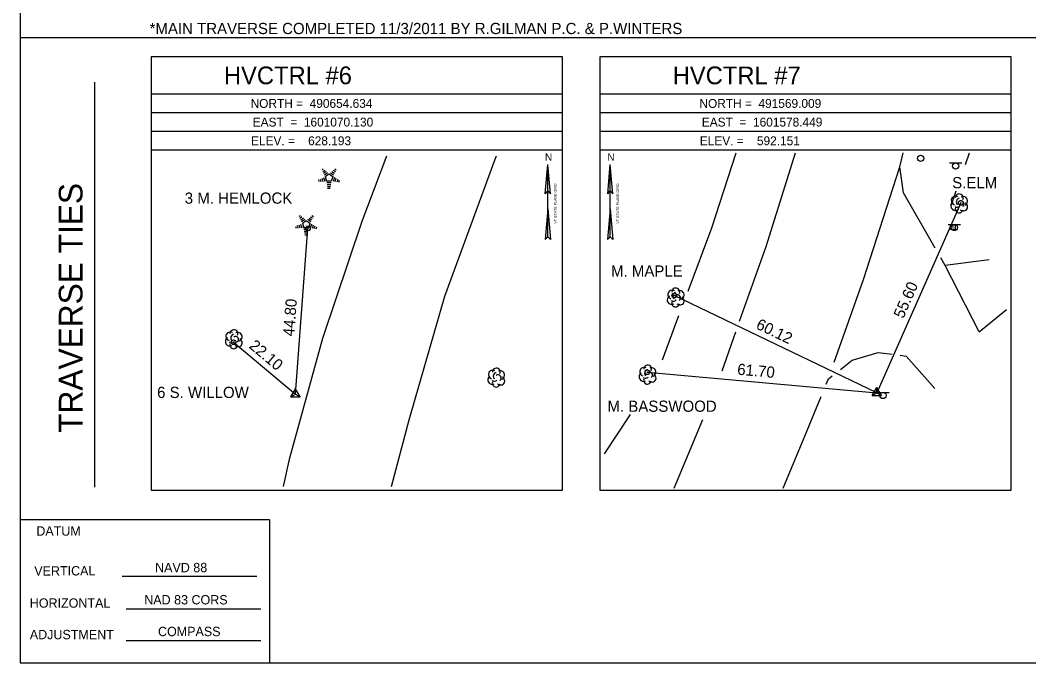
# Model space of a CAD drawing. Extents: x 1598730 to 1599370, y 501440 to 502728.
# Drawn here: x 1598729.5 to 1598999.2, y 502307.8 to 502479.8 of the extents above; entities that cross this region are included whole.
import ezdxf

# ---------------------------------------------------------------- set-up
doc = ezdxf.new("R2010")
doc.units = 0
for name, color, linetype in [('CBP', 7, 'Continuous'), ('CPSM', 7, 'Continuous'), ('Default', 7, 'Continuous'), ('L_C', 7, 'Continuous'), ('LAWA', 7, 'Continuous'), ('LTC', 7, 'Continuous'), ('LTD', 7, 'Continuous'), ('NBL1', 7, 'Continuous'), ('NBL2', 7, 'Continuous'), ('NNA_P', 7, 'Continuous'), ('PET', 7, 'Continuous'), ('RDG', 7, 'Continuous'), ('SRM', 7, 'Continuous'), ('SSGN', 7, 'Continuous'), ('UTMH', 7, 'Continuous')]:
    doc.layers.add(name, color=color, linetype=linetype)

msp = doc.modelspace()

# ---------------------------------------------------------------- linework, layer by layer
at = {"layer": 'CBP'}
for centre, radius in [((1598981.02, 502430.88), 0.625), ((1598981.02, 502430.88), 0.0833), ((1598806.48, 502424.07), 0.625), ((1598806.48, 502424.07), 0.0833), ((1598904.42, 502406.08), 0.625), ((1598904.42, 502406.08), 0.0833), ((1598786.58, 502393.61), 0.625), ((1598786.58, 502393.61), 0.0833), ((1598897.23, 502385.57), 0.625), ((1598897.23, 502385.57), 0.0833)]:
    msp.add_circle(centre, radius, dxfattribs=at)
at = {"layer": 'CPSM'}
for p, q in [((1598801.88, 502379.01), (1598803.13, 502381.17)), ((1598801.88, 502379.01), (1598803.13, 502379.73)), ((1598804.38, 502379.01), (1598803.13, 502381.17)), ((1598803.13, 502379.73), (1598803.13, 502381.17)), ((1598803.13, 502379.73), (1598803.13, 502379.73)), ((1598803.13, 502379.73), (1598804.38, 502379.01)), ((1598957.38, 502379.35), (1598958.63, 502381.52)), ((1598957.38, 502379.35), (1598958.63, 502380.08)), ((1598959.88, 502379.35), (1598958.63, 502381.52)), ((1598958.63, 502380.08), (1598958.63, 502381.52)), ((1598958.63, 502380.08), (1598958.63, 502380.08)), ((1598958.63, 502380.08), (1598959.88, 502379.35)), ((1598801.88, 502379.01), (1598804.38, 502379.01)), ((1598957.38, 502379.35), (1598959.88, 502379.35))]:
    msp.add_line(p, q, dxfattribs=at)
at = {"layer": 'Default'}
for p, q in [((1598981.02, 502430.88), (1598958.63, 502380.08)), ((1598803.13, 502379.73), (1598806.48, 502424.07)), ((1598958.63, 502380.08), (1598904.42, 502406.08)), ((1598786.58, 502393.61), (1598803.13, 502379.73)), ((1598897.23, 502385.57), (1598958.63, 502380.08))]:
    msp.add_line(p, q, dxfattribs=at)
at = {"layer": 'LAWA'}
for points in [[(1598908.11, 502407.27), (1598914.45, 502424.21), (1598921, 502444.27)], [(1598982.3, 502441.19), (1598983.37, 502444.27)], [(1598978.51, 502430.36), (1598979.83, 502434.12)], [(1598901.24, 502388.92), (1598905.65, 502400.72)], [(1598885.77, 502363.77), (1598892.69, 502374.3)]]:
    msp.add_lwpolyline(points, dxfattribs=at)
at = {"layer": 'LTC'}
for p, q in [((1598810.24, 502439.76), (1598810.59, 502440.02)), ((1598810.45, 502439.29), (1598810.98, 502439.68)), ((1598810.66, 502438.83), (1598811.36, 502439.34)), ((1598810.87, 502438.36), (1598811.75, 502439)), ((1598812.52, 502438.96), (1598813.33, 502438.37)), ((1598812.9, 502439.3), (1598813.57, 502438.81)), ((1598813.27, 502439.65), (1598813.82, 502439.25)), ((1598813.64, 502440), (1598814.06, 502439.7)), ((1598809.27, 502437.04), (1598809.42, 502436.57)), ((1598809.73, 502437.26), (1598809.94, 502436.6)), ((1598810.18, 502437.47), (1598810.45, 502436.64)), ((1598810.64, 502437.69), (1598810.97, 502436.67)), ((1598811.09, 502437.91), (1598812.1, 502438.64)), ((1598811.09, 502437.91), (1598811.48, 502436.71)), ((1598812.71, 502436.71), (1598811.48, 502436.71)), ((1598812.67, 502436.21), (1598811.53, 502436.21)), ((1598812.1, 502438.64), (1598813.1, 502437.92)), ((1598813.1, 502437.92), (1598812.71, 502436.71)), ((1598813.54, 502437.65), (1598813.2, 502436.61)), ((1598813.98, 502437.4), (1598813.7, 502436.51)), ((1598814.43, 502437.15), (1598814.19, 502436.42)), ((1598814.87, 502436.9), (1598814.69, 502436.32)), ((1598812.59, 502435.71), (1598811.6, 502435.71)), ((1598812.5, 502435.21), (1598811.67, 502435.21)), ((1598812.42, 502434.71), (1598811.75, 502434.71)), ((1598804.12, 502427.3), (1598804.48, 502427.55)), ((1598804.33, 502426.83), (1598804.86, 502427.21)), ((1598804.54, 502426.36), (1598805.25, 502426.88)), ((1598804.75, 502425.9), (1598805.63, 502426.54)), ((1598804.98, 502425.44), (1598805.99, 502426.18)), ((1598804.98, 502425.44), (1598805.36, 502424.25)), ((1598805.99, 502426.18), (1598806.99, 502425.45)), ((1598806.41, 502426.49), (1598807.22, 502425.9)), ((1598806.99, 502425.45), (1598806.59, 502424.25)), ((1598806.78, 502426.84), (1598807.46, 502426.35)), ((1598807.15, 502427.19), (1598807.7, 502426.79)), ((1598807.52, 502427.54), (1598807.94, 502427.23)), ((1598803.16, 502424.58), (1598803.31, 502424.11)), ((1598803.61, 502424.79), (1598803.82, 502424.14)), ((1598804.07, 502425.01), (1598804.34, 502424.17)), ((1598804.52, 502425.22), (1598804.85, 502424.21)), ((1598806.59, 502424.25), (1598805.36, 502424.25)), ((1598806.56, 502423.75), (1598805.41, 502423.75)), ((1598806.47, 502423.25), (1598805.48, 502423.25)), ((1598806.39, 502422.75), (1598805.56, 502422.75)), ((1598807.42, 502425.18), (1598807.09, 502424.14)), ((1598807.87, 502424.93), (1598807.58, 502424.05)), ((1598808.31, 502424.68), (1598808.08, 502423.95)), ((1598808.76, 502424.43), (1598808.57, 502423.86)), ((1598806.3, 502422.25), (1598805.63, 502422.25))]:
    msp.add_line(p, q, dxfattribs=at)
at = {"layer": 'LTD'}
for p, q in [((1598980.58, 502430.79), (1598980.58, 502430.79)), ((1598980.58, 502430.79), (1598980.58, 502430.79)), ((1598904.79, 502405.63), (1598904.79, 502405.63)), ((1598904.79, 502405.63), (1598904.79, 502405.63)), ((1598786.62, 502394.45), (1598786.62, 502394.45)), ((1598786.62, 502394.45), (1598786.62, 502394.45)), ((1598897.27, 502384.99), (1598897.27, 502384.99)), ((1598897.27, 502384.99), (1598897.27, 502384.99)), ((1598856.81, 502384.21), (1598856.81, 502384.21)), ((1598856.81, 502384.21), (1598856.81, 502384.21))]:
    msp.add_line(p, q, dxfattribs=at)
for centre in [(1598980.62, 502432.22), (1598904.83, 502407.06), (1598786.67, 502395.89), (1598856.86, 502385.64), (1598897.31, 502386.43)]:
    msp.add_arc(centre, 1.05, 335.5272, 180.9563, dxfattribs=at)
for centre, major_axis, ratio, start_param, end_param in [((1598979.49, 502430.08), (0.58, -1.04), 0.959034, 3.141593, 6.283185), ((1598979.79, 502431.46), (1.21, -0.51), 0.895232, 1.570796, 4.712389), ((1598980.37, 502431.25), (-0.208, -0.792), 0.645439, 3.141593, 6.283185), ((1598981.08, 502430.62), (-0.5, 0.667), 0.989748, 3.141593, 6.283185), ((1598981.58, 502429.96), (-1.09, 0.79), 0.841452, 1.570796, 4.712389), ((1598981.62, 502431.37), (-1.14, -0.48), 0.949671, 1.570796, 4.712389), ((1598980.58, 502429.29), (0.26, 1.06), 0.942809, 1.570796, 4.712389), ((1598980.12, 502430.04), (-0.625, -0.083), 0.423636, 0, 3.141593), ((1598903.99, 502406.3), (1.21, -0.51), 0.895232, 1.570796, 4.712389), ((1598904.58, 502406.09), (-0.208, -0.792), 0.645439, 3.141593, 6.283185), ((1598905.83, 502406.21), (-1.14, -0.48), 0.949671, 1.570796, 4.712389), ((1598903.7, 502404.92), (0.58, -1.04), 0.959034, 3.141593, 6.283185), ((1598904.79, 502404.13), (0.26, 1.06), 0.942809, 1.570796, 4.712389), ((1598904.33, 502404.88), (-0.625, -0.083), 0.423636, 0, 3.141593), ((1598905.29, 502405.46), (-0.5, 0.667), 0.989748, 3.141593, 6.283185), ((1598905.79, 502404.8), (-1.09, 0.79), 0.841452, 1.570796, 4.712389), ((1598785.83, 502395.12), (1.21, -0.51), 0.895232, 1.570796, 4.712389), ((1598786.41, 502394.91), (-0.208, -0.792), 0.645439, 3.141593, 6.283185), ((1598787.66, 502395.04), (-1.14, -0.48), 0.949671, 1.570796, 4.712389), ((1598785.54, 502393.75), (0.58, -1.04), 0.959034, 3.141593, 6.283185), ((1598786.62, 502392.95), (0.26, 1.06), 0.942809, 1.570796, 4.712389), ((1598786.16, 502393.7), (-0.625, -0.083), 0.423636, 0, 3.141593), ((1598787.12, 502394.29), (-0.5, 0.667), 0.989748, 3.141593, 6.283185), ((1598787.62, 502393.62), (-1.09, 0.79), 0.841452, 1.570796, 4.712389), ((1598856.02, 502384.88), (1.21, -0.51), 0.895232, 1.570796, 4.712389), ((1598856.6, 502384.67), (-0.208, -0.792), 0.645439, 3.141593, 6.283185), ((1598857.31, 502384.04), (-0.5, 0.667), 0.989748, 3.141593, 6.283185), ((1598857.85, 502384.79), (-1.14, -0.48), 0.949671, 1.570796, 4.712389), ((1598896.18, 502384.29), (0.58, -1.04), 0.959034, 3.141593, 6.283185), ((1598896.48, 502385.66), (1.21, -0.51), 0.895232, 1.570796, 4.712389), ((1598897.06, 502385.45), (-0.208, -0.792), 0.645439, 3.141593, 6.283185), ((1598897.77, 502384.83), (-0.5, 0.667), 0.989748, 3.141593, 6.283185), ((1598898.27, 502384.16), (-1.09, 0.79), 0.841452, 1.570796, 4.712389), ((1598898.31, 502385.58), (-1.14, -0.48), 0.949671, 1.570796, 4.712389), ((1598855.73, 502383.5), (0.58, -1.04), 0.959034, 3.141593, 6.283185), ((1598856.81, 502382.71), (0.26, 1.06), 0.942809, 1.570796, 4.712389), ((1598856.35, 502383.46), (-0.625, -0.083), 0.423636, 0, 3.141593), ((1598857.81, 502383.38), (-1.09, 0.79), 0.841452, 1.570796, 4.712389), ((1598897.27, 502383.49), (0.26, 1.06), 0.942809, 1.570796, 4.712389), ((1598896.81, 502384.24), (-0.625, -0.083), 0.423636, 0, 3.141593)]:
    msp.add_ellipse(centre, major_axis=major_axis, ratio=ratio, start_param=start_param, end_param=end_param, dxfattribs=at)
at = {"layer": 'NBL1'}
msp.add_lwpolyline([(1598729.53, 502307.83), (1599369.53, 502307.83), (1599369.53, 502727.83), (1598729.53, 502727.83)], close=True, dxfattribs=at)
at = {"layer": 'NBL2'}
for p, q in [((1598729.53, 502475.17), (1599369.53, 502475.17)), ((1598749.53, 502354.83), (1598749.53, 502463.17)), ((1598874.53, 502460), (1598764.53, 502460)), ((1598994.53, 502460), (1598884.53, 502460)), ((1598874.53, 502455), (1598764.53, 502455)), ((1598994.53, 502455), (1598884.53, 502455)), ((1598874.53, 502450), (1598764.53, 502450)), ((1598994.53, 502450), (1598884.53, 502450)), ((1598874.53, 502445), (1598764.53, 502445)), ((1598994.53, 502445), (1598884.53, 502445)), ((1598796.2, 502346.08), (1598729.53, 502346.08)), ((1598796.2, 502346.08), (1598796.2, 502307.83)), ((1598796.2, 502346.08), (1598796.2, 502307.83)), ((1598756.77, 502331.06), (1598792.77, 502331.03)), ((1598757.88, 502322.29), (1598793.88, 502322.29)), ((1598757.88, 502313.85), (1598793.88, 502313.82))]:
    msp.add_line(p, q, dxfattribs=at)
for points in [[(1598764.53, 502354), (1598874.53, 502354), (1598874.53, 502470), (1598764.53, 502470)], [(1598884.53, 502354), (1598994.53, 502354), (1598994.53, 502470), (1598884.53, 502470)]]:
    msp.add_lwpolyline(points, close=True, dxfattribs=at)
at = {"layer": 'NNA_P'}
for p, q in [((1598869.93, 502433.35), (1598870.63, 502441.14)), ((1598870.63, 502421.77), (1598870.63, 502441.14)), ((1598871.32, 502433.35), (1598870.63, 502441.14)), ((1598886.62, 502433.35), (1598887.32, 502441.14)), ((1598887.32, 502421.77), (1598887.32, 502441.14)), ((1598888.01, 502433.35), (1598887.32, 502441.14)), ((1598869.93, 502433.35), (1598870.63, 502434.12)), ((1598871.32, 502433.35), (1598870.63, 502434.12)), ((1598886.62, 502433.35), (1598887.32, 502434.12)), ((1598888.01, 502433.35), (1598887.32, 502434.12)), ((1598870.63, 502429.29), (1598869.91, 502421.13)), ((1598870.63, 502429.29), (1598871.35, 502421.13)), ((1598887.32, 502429.29), (1598886.6, 502421.13)), ((1598887.32, 502429.29), (1598888.04, 502421.13)), ((1598870.63, 502421.77), (1598869.91, 502421.13)), ((1598870.63, 502421.77), (1598871.35, 502421.13)), ((1598887.32, 502421.77), (1598886.6, 502421.13)), ((1598887.32, 502421.77), (1598888.04, 502421.13))]:
    msp.add_line(p, q, dxfattribs=at)
at = {"layer": 'PET'}
for points in [[(1598921.91, 502399.26), (1598928.98, 502419.2), (1598936.86, 502444.27)], [(1598947.22, 502388.26), (1598955.06, 502410.39), (1598964.72, 502440.57), (1598965.59, 502444.27)], [(1598799.92, 502355.02), (1598801.66, 502362.66), (1598810.44, 502394.69), (1598821.01, 502426.01), (1598827.59, 502443.48)], [(1598828.8, 502355.02), (1598833.5, 502372.83), (1598843.12, 502405.9), (1598856.55, 502442.57), (1598856.93, 502443.48)], [(1598974.22, 502418.73), (1598965.75, 502433.54), (1598964.72, 502440.57)], [(1598985.94, 502396.4), (1598976.87, 502414.09), (1598975.69, 502416.15)], [(1598917.2, 502385.96), (1598920.9, 502396.4)], [(1598948.84, 502386.32), (1598952.02, 502388.8), (1598958.94, 502390.82), (1598962.68, 502390.37)], [(1598964.85, 502390.1), (1598966.41, 502389.91), (1598974.13, 502381.22)], [(1598945.07, 502382.4), (1598945.66, 502383.84)], [(1598945.66, 502383.84), (1598946.65, 502384.61)], [(1598933.57, 502354.6), (1598939.98, 502370.03), (1598943.7, 502379.06)], [(1598904.36, 502354.6), (1598912.09, 502372.91)]]:
    msp.add_lwpolyline(points, dxfattribs=at)
at = {"layer": 'RDG'}
for points in [[(1598988.65, 502415.66), (1598976.87, 502414.09)], [(1598985.94, 502396.4), (1598993.22, 502402.4)]]:
    msp.add_lwpolyline(points, dxfattribs=at)
at = {"layer": 'SRM'}
msp.add_lwpolyline([(1598978.29, 502425.05), (1598979.54, 502425.05), (1598979.54, 502423.8), (1598978.29, 502423.8)], close=True, dxfattribs=at)
msp.add_circle((1598978.91, 502424.43), 0.0833, dxfattribs=at)
at = {"layer": 'SSGN'}
for p, q in [((1598978.01, 502441.57), (1598981.34, 502441.57)), ((1598979.66, 502440.74), (1598979.66, 502440.74)), ((1598977.64, 502425.13), (1598980.98, 502425.13)), ((1598979.29, 502424.29), (1598979.29, 502424.29)), ((1598958.57, 502380.19), (1598961.9, 502380.19)), ((1598960.21, 502379.36), (1598960.21, 502379.36))]:
    msp.add_line(p, q, dxfattribs=at)
for centre in [(1598979.66, 502440.74), (1598979.29, 502424.29), (1598960.21, 502379.36)]:
    msp.add_circle(centre, 0.833, dxfattribs=at)
at = {"layer": 'UTMH'}
for p, q in [((1598970.28, 502442.8), (1598970.28, 502442.8)), ((1598971.12, 502442.8), (1598971.12, 502442.8))]:
    msp.add_line(p, q, dxfattribs=at)
msp.add_circle((1598970.28, 502442.8), 0.833, dxfattribs=at)

# ---------------------------------------------------------------- texts
at = {"layer": 'Default'}
msp.add_text('*MAIN TRAVERSE COMPLETED 11/3/2011 BY R.GILMAN P.C. & P.WINTERS', height=3, dxfattribs=at).set_placement((1598764.13, 502476.04))
for s, rotation, p in [('55.60', 66.2173, (1598965.66, 502399.75)), ('44.80', 85.6808, (1598802.79, 502395.11)), ('60.12', 334.3742, (1598926.05, 502397.37)), ('22.10', 319.9955, (1598790.52, 502392.27)), ('61.70', 354.8864, (1598921.17, 502384.93))]:
    msp.add_text(s, height=3, rotation=rotation, dxfattribs=at).set_placement(p)
at = {"layer": 'L_C'}
for s, p in [('S.ELM', (1598978.74, 502434.79)), ('3 M. HEMLOCK', (1598773.55, 502430.66)), ('M. MAPLE', (1598887.52, 502411.15)), ('6 S. WILLOW', (1598766.15, 502378.69)), ('M. BASSWOOD', (1598886.57, 502374.99))]:
    msp.add_text(s, height=3, dxfattribs=at).set_placement(p)
at = {"layer": 'LTC'}
for p in [(1598811.99, 502437.66), (1598805.87, 502425.19)]:
    msp.add_text('.', height=1.04, rotation=270, dxfattribs=at).set_placement(p)
at = {"layer": 'NBL2'}
for s, height, p in [('     HVCTRL #6     ', 4.75, (1598775.18, 502462.62)), ('     HVCTRL #7     ', 4.75, (1598895.18, 502462.62)), ('NORTH =  490654.634 ', 2.375, (1598791.15, 502456.31)), ('NORTH =  491569.009 ', 2.375, (1598911.15, 502456.31)), ('EAST  =  1601070.130', 2.375, (1598791.71, 502451.31)), ('EAST  =  1601578.449', 2.375, (1598911.8, 502451.31)), ('ELEV. =    628.193  ', 2.375, (1598791.26, 502446.31)), ('ELEV. =    592.151  ', 2.375, (1598911.26, 502446.31)), ('DATUM', 2.5, (1598733.85, 502341.85)), ('  NAVD 88 ', 2.5, (1598763.75, 502332.07)), ('NAD 83 CORS', 2.5, (1598762.71, 502323.46)), ('HORIZONTAL', 2.5, (1598732.11, 502322.58)), ('  COMPASS ', 2.5, (1598764.53, 502314.97)), ('ADJUSTMENT', 2.5, (1598732.11, 502314.15))]:
    msp.add_text(s, height=height, dxfattribs=at).set_placement(p)
for s, height, rotation, p in [('TRAVERSE TIES', 6.3332, 90, (1598746.2, 502369.38)), ('VERTICAL', 2.5, 0.1439, (1598733.31, 502331.18))]:
    msp.add_text(s, height=height, rotation=rotation, dxfattribs=at).set_placement(p)
at = {"layer": 'NNA_P'}
for p in [(1598869.87, 502442.15), (1598886.56, 502442.15)]:
    msp.add_text('N', height=1.97, dxfattribs=at).set_placement(p)
for p in [(1598872.98, 502425.33), (1598889.67, 502425.33)]:
    msp.add_text('VT STATE PLANE GRID', height=0.7, rotation=90.0204, dxfattribs=at).set_placement(p)

doc.saveas('drawing.dxf')
